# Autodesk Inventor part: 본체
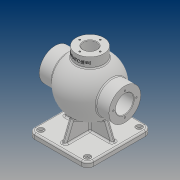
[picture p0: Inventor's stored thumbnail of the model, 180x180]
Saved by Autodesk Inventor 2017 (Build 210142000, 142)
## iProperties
Part Number: 본체
Material: 일반
Document SubType Name: Modeling
Designer: 13
Density: 1 g/cm^3
Appearance: 기본값
Mass: 557.04 g
Surface Area: 1153.86 cm^2
Volume: 557.04 cm^3
Author: 13
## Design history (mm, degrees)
revolve "회전1" stored, may be unused: angle "d13" = 90 deg
node "작업 평면1"
sketch "스케치3"
  geometry: L1 (-57.5, 62.5)-(57.5, 62.5); L2 (57.5, 62.5)-(57.5, -62.5); L3 (57.5, -62.5)-(-57.5, -62.5); L4 (-57.5, -62.5)-(-57.5, 62.5); L5 (-57.5, 62.5)-(57.5, -62.5); L6 (57.5, 62.5)-(-57.5, -62.5); 1 further point
  constraints: 12 end point, 2 midpoint, 2 parallel, 1 horizontal, 1 perpendicular
  dimensions: "d20" = 115 distance of L2.end L3.end; "d21" = 125 distance of L1.end L2.end
extrude "돌출1" join sketch "스케치3" distance "d22" = 10; taper "d23" = 0 deg
sketch "스케치4"
  geometry: L1 (-47.5, 4)-(47.5, 4); L2 (47.5, 4)-(47.5, -4); L3 (47.5, -4)-(-47.5, -4); L4 (-47.5, -4)-(-47.5, 4); L5 (-47.5, 4)-(47.5, -4); L6 (47.5, 4)-(-47.5, -4); L7 (-4, 52.5)-(4, 52.5); L8 (4, 52.5)-(4, -52.5); L9 (4, -52.5)-(-4, -52.5); L10 (-4, -52.5)-(-4, 52.5); L11 (-4, 52.5)-(4, -52.5); L12 (4, 52.5)-(-4, -52.5); L13 (57.5, 62.5)-(57.5, -62.5) reference; L14 (-57.5, 62.5)-(57.5, 62.5) reference; 1 further point
  constraints: 24 end point, 4 midpoint, 4 parallel, 2 horizontal, 2 perpendicular
  dimensions: "d24" = 8 distance of L1.end L2.end; "d25" = 8 distance of L7.start L7.end; "d26" = 10 distance between parallel lines of L2 L13; "d27" = 10 distance between parallel lines of L14 L7
extrude "돌출2" join sketch "스케치4" stored distance "d28" = 10; taper "d29" = 0 deg
feature "면 기울기1" dims angle "d30" = 22 deg
fillet "모깎기1" dims "d31" = 3
fillet "모깎기2" dims "d32" = 3
fillet "모깎기3" dims "d33" = 3
fillet "모깎기4" dims "d34" = 3
node "작업 평면2"
sketch "스케치5"
  geometry: C1 r 27 at (0, 0); 1 further point
  constraints: 1 centre point, 1 coincident
  dimensions: "d36" = 54 diameter of C1
extrude "돌출3" join sketch "스케치5" stored distance "d37" = 10; taper "d38" = 0 deg
sketch "스케치6"
  geometry: C1 r 13 at (0, 0); 1 further point
  constraints: 1 centre point, 1 coincident
  dimensions: "d39" = 26 diameter of C1
extrude "돌출4" cut sketch "스케치6" distance "d40" = 30; taper "d41" = 0 deg
fillet "모깎기5" dims "d42" = 12
fillet "모깎기6" dims "d43" = 3
chamfer "모따기1" distance "d44" = 1; stored, may be unused: second distance "d45" = 2, angle "d46" = 45 deg
fillet "모깎기7" dims "d47" = 3
sketch "스케치8"
  geometry: L1 (-45.5, -62.5)-(45.5, -62.5) reference; L2 (57.5, -50.5)-(57.5, 50.5) reference; C1 r 6 at (45.5, -50.5); 1 further point
  constraints: 1 centre point
  dimensions: "d48" = 12 diameter of C1; "d50" = 12 distance from line of L2 C1.centre; "d51" = 12 distance from line of L1 C1.centre
extrude "돌출5" cut sketch "스케치8" distance "d52" = 3; taper "d53" = 0 deg
sketch "스케치9"
  geometry: L1 (12, 101)-(12, 0) reference; L2 (0, -12)-(-91, -12) reference; C1 r 4 at (0, 0); 1 further point
  constraints: 1 centre point
  dimensions: "d54" = 8 diameter of C1; "d55" = 12 distance from line of L1 C1.centre; "d56" = 12 distance from line of L2 C1.centre
extrude "돌출6" cut sketch "스케치9" stored distance "d57" = 3; taper "d58" = 0 deg
sketch "스케치11"
  geometry: 2 further points
  constraints: 1 horizontal alignment
  dimensions: "d65" = 22.5 distance of point (0, 0) point (-22.5, 0)
hole "구멍1" sketch "스케치11" at (-22.5, 0) diameter "d66" = 3.242; stored, may be unused: countersink angle "d70" = 90 deg, drill point angle "d72" = 118 deg; dims "d67" = 12, "d68" = 4, "d69" = 2, "d71" = 15
sketch "스케치12"
  geometry: 2 further points
  constraints: 1 horizontal alignment
  dimensions: "d76" = 24 distance of point (0, 0) point (24, 0)
hole "구멍2" sketch "스케치12" at (24, 0) diameter "d77" = 3.242; stored, may be unused: countersink angle "d81" = 90 deg, drill point angle "d83" = 118 deg; dims "d78" = 16, "d79" = 4, "d80" = 2, "d82" = 19
sketch "스케치13"
  geometry: 2 further points
  constraints: 1 vertical alignment
  dimensions: "d87" = 20 distance of point (0, 0) point (0, 20)
hole "구멍3" sketch "스케치13" at (0, 20) diameter "d88" = 3.242; stored, may be unused: countersink angle "d92" = 90 deg, drill point angle "d94" = 118 deg; dims "d89" = 9, "d90" = 4, "d91" = 2, "d93" = 11
node "작업 평면3"
sketch "스케치14"
  geometry: L1 (-27, 65)-(27, 65) reference; L2 (-27, 65)-(-27, 50.285); L3 (-27, 65)-(-27, 47.286) reference; 2 further points
  constraints: 2 end point, 1 point on line, 1 other
  dimensions: "d103" = 10 distance from line of point (0, 55) L1; "d104" = 27 distance from line of L2 point (0, 55)
feature "엠보싱2" sketch "스케치14" dims "d1" = 136, "d8" = 106, "d9" = 86, "d11" = 62, "d17" = 35, "d101" = 0.5, "d102" = 0, "d105" = 16, "d106" = 1.75, "d107" = 37, "d108" = 35
node "솔리드1"
pattern_linear "직사각형 패턴1" dims "d61" = 101, "d64" = 91
pattern_circular "원형 패턴3" dims angle "d96" = 360 deg
pattern_circular "원형 패턴4" dims angle "d110" = 360 deg
pattern_circular "원형 패턴5" dims angle "d113" = 360 deg
sketch "스케치2"
  geometry: L1 (68, 0)-(-68, 0); L2 (68, 31)-(42.988, 31); L3 (-42.988, 31)-(-68, 31); L4 (-68, 31)-(-68, 17.5); L5 (68, 31)-(68, 17.5); L6 (-68, 17.5)-(-52, 17.5); L7 (-52, 17.5)-(-39.278, 17.5); L8 (68, 17.5)-(52, 17.5); L9 (52, 17.5)-(52, 18.5); L10 (52, 18.5)-(50.25, 18.5); L11 (50.25, 18.5)-(50.25, 17.5); L12 (50.25, 17.5)-(39.278, 17.5); A1 r 53 centre (0, 0) between (42.988, 31) and (-42.988, 31); A2 r 43 centre (0, 0) between (39.278, 17.5) and (-39.278, 17.5); 6 further points
  constraints: 25 end point, 7 horizontal, 5 midpoint, 4 point on circle, 4 vertical, 3 coincident, 3 point on line, 2 centre point, 2 vertical alignment, 1 horizontal alignment
  dimensions: "d1" = 136 distance of L1.start L1.end; "d8" = 106 diameter of A1; "d9" = 86 diameter of A2; "d11" = 62 diameter of L3 L1; "d17" = 35 diameter of L6 L1; "d105" = 16 distance of L5.end L8.end; "d106" = 1.75 distance of L9.end L10.end; "d107" = 37 diameter of L10 L1; "d108" = 35 diameter of L8 L1
other parameters: "d2" = 106, "d19" = -85, "d35" = 65
